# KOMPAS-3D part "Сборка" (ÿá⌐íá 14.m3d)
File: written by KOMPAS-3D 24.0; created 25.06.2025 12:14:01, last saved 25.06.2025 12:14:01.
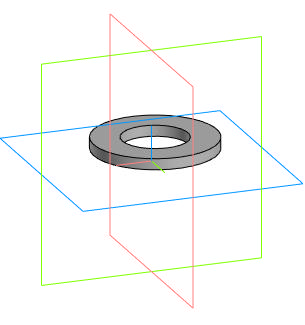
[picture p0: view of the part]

Document properties: Автор: PC321; Полное имя файла: C:\Для ноута\Инженерная графика\ППЭ 2025-2026\Варианты 1-38\Вариант 2 СБ\Решение 2\Вар 2 СБ\Шайба 14.m3d

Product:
- Component [standard]: Шайба A.14.37 ГОСТ 11371-78  | qty 1  | pos. 1  | Материал: АД1 ГОСТ 4784-97 (density 1000 kg/m3); Масса: 0.008612; Раздел спецификации: Стандартные изделия; Рассекать на разрезах: no
- Part/product: Сборка
    Масса: 0.008612

Referenced files in C:\Program Files\ASCON\KOMPAS-3D v21 Study\Libs\PARTLib\DATA\vault\Methods\Kompas\3D\: PLib_Washer_1_712.m3d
